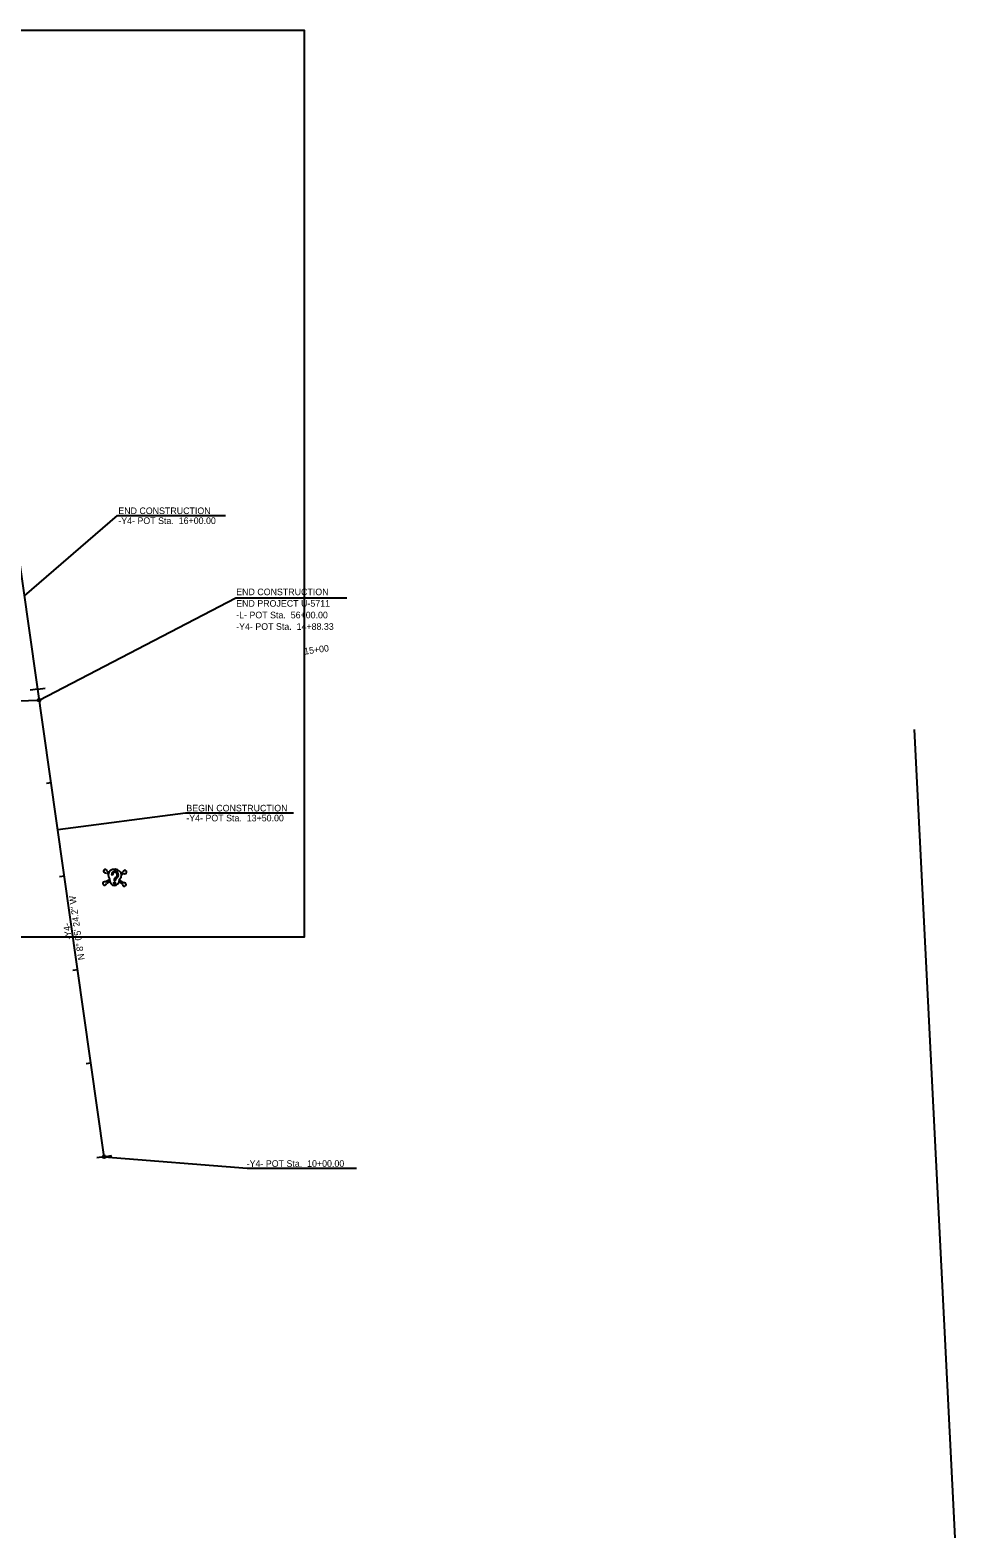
# Model space of a CAD drawing. Extents: x 1755545 to 1761252, y 736169 to 737766.
# Drawn here: x 1760273 to 1761252, y 736169 to 737766 of the extents above; entities that cross this region are included whole.
import ezdxf

# ---------------------------------------------------------------- set-up
doc = ezdxf.new("R2010")
doc.units = 0
for name, color, linetype in [('Default', 7, 'Continuous'), ('Prop Horizontal Alignment', 7, 'Continuous'), ('Prop Horizontal Alignment Direction Label', 7, 'Continuous'), ('Prop Horizontal Alignment Station Label', 7, 'Continuous'), ('Prop Horizontal Alignment Tick Label', 7, 'Continuous'), ('Prop Horizontal Alignment Tick Large', 7, 'Continuous'), ('Prop Horizontal Alignment Tick Small', 7, 'Continuous'), ('Scratch_Level_5', 7, 'Continuous')]:
    doc.layers.add(name, color=color, linetype=linetype)

msp = doc.modelspace()

# ---------------------------------------------------------------- linework, layer by layer
at = {"layer": 'Default'}
for p, q in [((1760353.3, 736873.6), (1760355.6, 736872)), ((1760354.3, 736875.1), (1760356.2, 736873.7)), ((1760371.3, 736874.2), (1760369.3, 736873.1)), ((1760357.1, 736866.2), (1760352.8, 736863.8)), ((1760357.4, 736864.3), (1760353.7, 736862.2)), ((1760359, 736871.5), (1760360.1, 736871.4)), ((1760361.8, 736866), (1760361.8, 736865)), ((1760361.8, 736865), (1760362.9, 736864.9)), ((1760362, 736866), (1760361.9, 736865)), ((1760362.2, 736866), (1760362.1, 736865)), ((1760362.3, 736866), (1760362.3, 736865)), ((1760362.5, 736865.9), (1760362.4, 736864.9)), ((1760362.5, 736868.8), (1760362.5, 736868.8)), ((1760362.6, 736865.9), (1760362.6, 736864.9)), ((1760362.8, 736865.9), (1760362.8, 736864.9)), ((1760363, 736865.9), (1760362.9, 736864.9)), ((1760367.2, 736863.9), (1760370.7, 736861.4)), ((1760367.7, 736865.7), (1760371.7, 736862.9)), ((1760372.2, 736872.7), (1760369.7, 736871.3))]:
    msp.add_line(p, q, dxfattribs=at)
for radius in [0.81, 0.63, 0.446, 0.266, 0.0863]:
    msp.add_circle((1760362.3, 736862.5), radius, dxfattribs=at)
for centre, start, end in [((1760352.4, 736875.3), 353.1242, 297.0327), ((1760373.2, 736874.3), 237.4204, 181.3289), ((1760351.8, 736862.2), 57.4204, 1.3289), ((1760372.6, 736861.2), 173.1242, 117.0327)]:
    msp.add_arc(centre, 1.9, start, end, dxfattribs=at)
for centre, major_axis, ratio, start_param, end_param in [((1760362.6, 736871.1), (7.1, -0.34), 0.885014, 5.564242, 10.143721), ((1760362.7, 736871.3), (0.2, 4.08), 0.9, 3.567618, 7.853982), ((1760362.7, 736871.3), (0.19, 3.9), 0.9, 3.567618, 7.853982), ((1760362.7, 736871.3), (0.18, 3.72), 0.9, 3.567618, 7.853982), ((1760362.7, 736871.3), (0.17, 3.54), 0.9, 3.567618, 7.853982), ((1760362.7, 736871.3), (0.16, 3.36), 0.9, 3.567618, 7.853982), ((1760362.7, 736871.3), (0.15, 3.18), 0.9, 3.567618, 7.853982), ((1760362.7, 736871.3), (0.15, 3), 0.9, 3.567618, 7.853982), ((1760362.7, 736871.3), (0.14, 2.82), 0.9, 3.567618, 7.853982), ((1760362.4, 736867), (-0.34, -7.1), 0.752542, 4.722735, 7.843636), ((1760364.6, 736865.8), (0.15, 3.06), 0.9, 0.426026, 1.570796), ((1760364.6, 736865.8), (0.14, 2.88), 0.9, 0.426026, 1.570796), ((1760364.6, 736865.8), (0.13, 2.7), 0.9, 0.426026, 1.570796), ((1760364.6, 736865.8), (0.12, 2.52), 0.9, 0.426026, 1.570796), ((1760364.6, 736865.8), (0.11, 2.34), 0.9, 0.426026, 1.570796), ((1760364.6, 736865.8), (0.1, 2.16), 0.9, 0.426026, 1.570796), ((1760364.6, 736865.8), (0.1, 1.98), 0.9, 0.426026, 1.570796), ((1760364.6, 736865.8), (0.09, 1.8), 0.9, 0.426026, 1.570796)]:
    msp.add_ellipse(centre, major_axis=major_axis, ratio=ratio, start_param=start_param, end_param=end_param, dxfattribs=at)
at = {"layer": 'Prop Horizontal Alignment'}
for p, q in [((1760351.4, 736572.9), (1760210.7, 737562.9)), ((1757285.6, 736971.2), (1760282.7, 737056.4))]:
    msp.add_line(p, q, dxfattribs=at)
at = {"layer": 'Prop Horizontal Alignment Station Label'}
for p, q in [((1760267, 737166.9), (1760365.6, 737252)), ((1760365.6, 737252), (1760479.7, 737252)), ((1760282.7, 737056.4), (1760490.7, 737164.8)), ((1760490.7, 737164.8), (1760608.1, 737164.8)), ((1760302.2, 736919.4), (1760437.6, 736937.1)), ((1760437.6, 736937.1), (1760551.8, 736937.1)), ((1760351.4, 736572.9), (1760502.9, 736560.6)), ((1760502.9, 736560.6), (1760618.6, 736560.6))]:
    msp.add_line(p, q, dxfattribs=at)
for centre in [(1760282.7, 737056.4), (1760351.4, 736572.9)]:
    msp.add_circle(centre, 1.5, dxfattribs=at)
at = {"layer": 'Prop Horizontal Alignment Tick Large'}
for p, q in [((1760281, 737067.9), (1760273.1, 737066.8)), ((1760281, 737067.9), (1760289, 737069)), ((1760351.4, 736572.9), (1760343.5, 736571.8)), ((1760351.4, 736572.9), (1760359.3, 736574))]:
    msp.add_line(p, q, dxfattribs=at)
at = {"layer": 'Prop Horizontal Alignment Tick Small'}
for p, q in [((1760295.1, 736968.9), (1760290.2, 736968.2)), ((1760309.2, 736869.9), (1760304.2, 736869.2)), ((1760323.3, 736770.9), (1760318.3, 736770.2)), ((1760337.3, 736671.9), (1760332.4, 736671.2))]:
    msp.add_line(p, q, dxfattribs=at)
at = {"layer": 'Scratch_Level_5'}
msp.add_line((1761208.8, 737025.1), (1761251.8, 736169.2), dxfattribs=at)
msp.add_lwpolyline([(1759122.4, 737765.9), (1760563.1, 737765.9), (1760563.1, 736805.4), (1759122.4, 736805.4)], close=True, dxfattribs=at)

# ---------------------------------------------------------------- texts
at = {"layer": 'Prop Horizontal Alignment Direction Label'}
for s, p in [('N 8%%d 05\' 24.2" W', (1760330.7, 736781.6)), ('-Y4-', (1760317.2, 736803.2))]:
    msp.add_text(s, height=7, rotation=98.09, dxfattribs=at).set_placement(p)
at = {"layer": 'Prop Horizontal Alignment Station Label'}
for s, p in [('END CONSTRUCTION', (1760366.3, 737253.4)), ('-Y4- POT Sta.  16+00.00', (1760366.3, 737242.9)), ('BEGIN CONSTRUCTION', (1760438.3, 736938.5)), ('-Y4- POT Sta.  13+50.00', (1760438.3, 736928))]:
    msp.add_text(s, height=7, dxfattribs=at).set_placement(p)
for s, p in [('END CONSTRUCTION', (1760491.1, 737167.5)), ('END PROJECT U-5711', (1760491.1, 737155.3)), ('-L- POT Sta.  56+00.00', (1760491.1, 737143)), ('-Y4- POT Sta.  14+88.33', (1760491.1, 737130.8)), ('-Y4- POT Sta.  10+00.00', (1760502.2, 736562.1))]:
    msp.add_text(s, height=7, rotation=360, dxfattribs=at).set_placement(p)
at = {"layer": 'Prop Horizontal Alignment Tick Label'}
msp.add_text('15+00', height=7, rotation=8.09, dxfattribs=at).set_placement((1760563.6, 737104.5))

doc.saveas('drawing.dxf')
